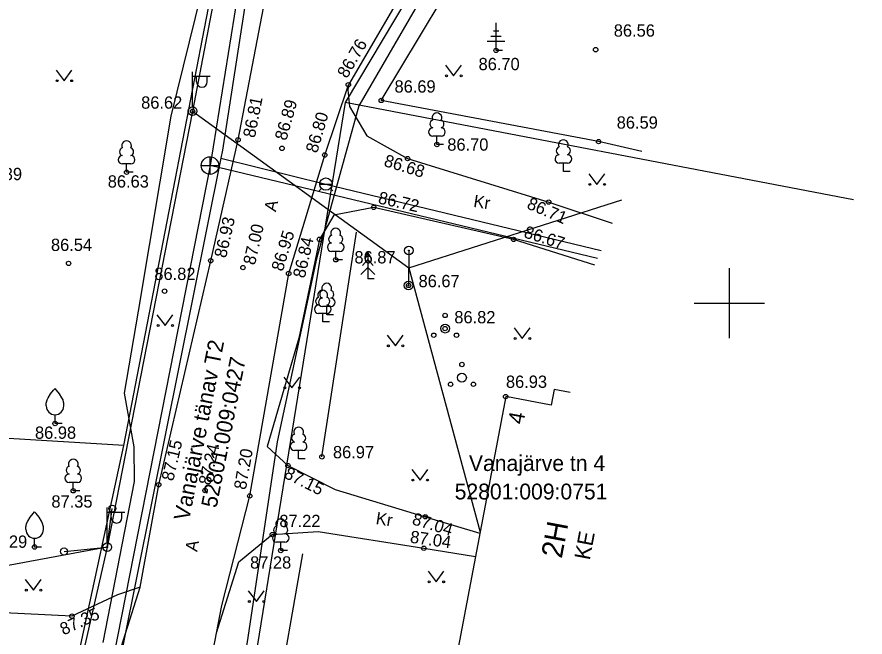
# Model space of a CAD drawing. Extents: x 648748 to 649126, y 6457789 to 6458252.
# Drawn here: x 648959.42 to 649007.73, y 6458080.98 to 6458116.31 of the extents above; entities that cross this region are included whole.
import ezdxf

# ---------------------------------------------------------------- set-up
doc = ezdxf.new("R2010")
doc.units = 0
for name, color, linetype in [('HALJASTUS', 7, 'Continuous'), ('HOONE', 7, 'Continuous'), ('KKAEV', 7, 'Continuous'), ('KORGUS-EH2000', 7, 'Continuous'), ('KTRASS', 7, 'Continuous'), ('MPOHULIIN', 7, 'Continuous'), ('PIIR', 7, 'Continuous'), ('POST', 7, 'Continuous'), ('PUU', 7, 'Continuous'), ('SITRASS', 7, 'Continuous'), ('TEE', 7, 'Continuous'), ('VKAEV', 7, 'Continuous'), ('VORK', 7, 'Continuous'), ('VTRASS', 7, 'Continuous')]:
    doc.layers.add(name, color=color, linetype=linetype)

msp = doc.modelspace()

# ---------------------------------------------------------------- linework, layer by layer
at = {"layer": 'HALJASTUS'}
for p, q in [((648961.649, 6458113.286), (648962.112, 6458112.679)), ((648962.112, 6458112.679), (648962.558, 6458113.286)), ((648983.834, 6458113.566), (648984.298, 6458112.96)), ((648984.298, 6458112.96), (648984.743, 6458113.566)), ((648992.001, 6458107.379), (648992.465, 6458106.772)), ((648992.465, 6458106.772), (648992.91, 6458107.379)), ((648976.796, 6458091.246), (648978.769, 6458104.056)), ((648967.4, 6458099.328), (648967.864, 6458098.722)), ((648967.864, 6458098.722), (648968.309, 6458099.328)), ((648987.742, 6458098.595), (648988.205, 6458097.988)), ((648988.205, 6458097.988), (648988.651, 6458098.595)), ((648980.518, 6458098.174), (648980.981, 6458097.568)), ((648980.981, 6458097.568), (648981.427, 6458098.174)), ((648974.626, 6458095.789), (648975.089, 6458095.183)), ((648975.089, 6458095.183), (648975.535, 6458095.789)), ((648981.92, 6458090.529), (648982.384, 6458089.923)), ((648982.384, 6458089.923), (648982.829, 6458090.529)), ((648982.84, 6458084.728), (648983.303, 6458084.121)), ((648983.303, 6458084.121), (648983.749, 6458084.728)), ((648959.895, 6458084.248), (648960.359, 6458083.642)), ((648960.359, 6458083.642), (648960.804, 6458084.248)), ((648972.6, 6458083.606), (648973.063, 6458082.999)), ((648973.063, 6458082.999), (648973.509, 6458083.606))]:
    msp.add_line(p, q, dxfattribs=at)
for points in [[(648995.014, 6458108.651), (648992.555, 6458109.206), (648980.179, 6458111.553), (648985.889, 6458121.059), (648992.136, 6458131.694), (648995.514, 6458136.968)], [(648972.606, 6458069.282), (648974.136, 6458076.713), (648975.715, 6458085.722)]]:
    msp.add_lwpolyline(points, dxfattribs=at)
for centre in [(648961.711, 6458112.679), (648962.54, 6458112.679), (648983.897, 6458112.96), (648984.726, 6458112.96), (648992.064, 6458106.772), (648992.893, 6458106.772), (648967.463, 6458098.722), (648968.292, 6458098.722), (648987.804, 6458097.988), (648988.633, 6458097.988), (648980.58, 6458097.568), (648981.409, 6458097.568), (648974.688, 6458095.183), (648975.517, 6458095.183), (648981.983, 6458089.923), (648982.812, 6458089.923), (648982.902, 6458084.121), (648983.731, 6458084.121), (648959.958, 6458083.642), (648960.787, 6458083.642), (648972.662, 6458082.999), (648973.491, 6458082.999)]:
    msp.add_circle(centre, 0.055, dxfattribs=at)
at = {"layer": 'HOONE'}
msp.add_lwpolyline([(648990.937, 6458094.909), (648990.022, 6458095.086), (648989.853, 6458094.19), (648987.264, 6458094.679), (648984.216, 6458078.561), (648986.916, 6458078.05), (648986.751, 6458077.176), (648988.913, 6458076.768)], dxfattribs=at)
at = {"layer": 'KKAEV'}
for p, q in [((648970.422, 6458107.342), (648970.422, 6458108.342)), ((648969.922, 6458107.842), (648970.922, 6458107.842))]:
    msp.add_line(p, q, dxfattribs=at)
msp.add_circle((648970.422, 6458107.842), 0.5, dxfattribs=at)
at = {"layer": 'KORGUS-EH2000'}
for centre in [(648986.716, 6458114.406), (648992.39, 6458114.447), (648978.301, 6458112.451), (648980.179, 6458111.553), (648969.428, 6458110.939), (648972.022, 6458109.308), (648992.555, 6458109.206), (648974.522, 6458108.824), (648983.347, 6458109.043), (648976.958, 6458108.444), (648981.678, 6458108.238), (648965.668, 6458107.461), (648979.746, 6458105.46), (648989.713, 6458105.763), (648976.658, 6458103.639), (648987.716, 6458103.635), (648977.582, 6458102.473), (648962.363, 6458102.27), (648970.461, 6458102.422), (648972.295, 6458102.031), (648974.902, 6458101.691), (648981.734, 6458101.01), (648967.833, 6458100.686), (648983.814, 6458098.551), (648987.264, 6458094.679), (648961.593, 6458093.144), (648976.796, 6458091.246), (648974.858, 6458090.743), (648967.5, 6458089.655), (648962.634, 6458089.31), (648970.142, 6458089.327), (648972.682, 6458089.018), (648982.682, 6458087.834), (648973.97, 6458086.815), (648960.43, 6458086.106), (648982.601, 6458086.036), (648974.448, 6458085.905), (648962.555, 6458082.165)]:
    msp.add_circle(centre, 0.125, dxfattribs=at)
at = {"layer": 'KTRASS'}
for p, q in [((648975.244, 6458137.772), (648970.422, 6458107.842)), ((648970.422, 6458107.842), (648961.748, 6458063.747)), ((648992.504, 6458102.546), (648970.422, 6458107.842))]:
    msp.add_line(p, q, dxfattribs=at)
at = {"layer": 'MPOHULIIN'}
msp.add_line((648964.567, 6458086.1), (648917.398, 6458077.299), dxfattribs=at)
for points in [[(648980.689, 6458168.372), (648973.79, 6458133.816), (648969.428, 6458110.939), (648964.567, 6458086.1), (648960.388, 6458067.751), (648949.192, 6458062.065)], [(648969.428, 6458110.939), (648981.739, 6458102.008), (648985.804, 6458086.956)], [(648981.739, 6458102.008), (648993.878, 6458105.888)]]:
    msp.add_lwpolyline(points, dxfattribs=at)
at = {"layer": 'PIIR'}
for p, q in [((649001.06, 6458149.93), (648978.12, 6458111.43)), ((648965.52, 6458091.89), (648973.5, 6458133.18)), ((648978.12, 6458111.43), (648971.21, 6458068.79)), ((649007.07, 6458105.881), (648978.12, 6458111.43)), ((648965.52, 6458091.89), (648918.81, 6458094.69)), ((648955.2, 6458044.42), (648965.52, 6458091.89))]:
    msp.add_line(p, q, dxfattribs=at)
at = {"layer": 'POST'}
for p, q in [((648969.428, 6458111.189), (648969.428, 6458113.189)), ((648969.428, 6458112.939), (648970.428, 6458112.939)), ((648969.655, 6458112.618), (648969.655, 6458112.939)), ((648970.268, 6458112.618), (648970.268, 6458112.939)), ((648981.744, 6458103.006), (648981.734, 6458101.01)), ((648964.567, 6458086.35), (648964.567, 6458088.35)), ((648964.567, 6458088.1), (648965.567, 6458088.1)), ((648964.793, 6458087.779), (648964.793, 6458088.1)), ((648965.406, 6458087.779), (648965.406, 6458088.1))]:
    msp.add_line(p, q, dxfattribs=at)
msp.add_lwpolyline([(648962.105, 6458085.851), (648964.567, 6458086.1), (648964.852, 6458088.295)], dxfattribs=at)
for centre, radius in [((648969.428, 6458110.939), 0.25), ((648969.428, 6458110.939), 0.0234), ((648981.744, 6458103.006), 0.25), ((648981.744, 6458103.006), 0.0234), ((648981.734, 6458101.01), 0.25), ((648981.734, 6458101.01), 0.0234), ((648964.852, 6458088.295), 0.2), ((648964.567, 6458086.1), 0.25), ((648962.105, 6458085.851), 0.2), ((648964.567, 6458086.1), 0.0234)]:
    msp.add_circle(centre, radius, dxfattribs=at)
for centre in [(648969.961, 6458112.618), (648965.1, 6458087.779)]:
    msp.add_arc(centre, 0.306, 180, 0, dxfattribs=at)
at = {"layer": 'PUU'}
for p, q in [((648986.716, 6458114.406), (648986.716, 6458115.981)), ((648987.016, 6458115.206), (648986.416, 6458115.206)), ((648986.866, 6458115.506), (648986.566, 6458115.506)), ((648987.216, 6458114.906), (648986.216, 6458114.906)), ((648987.076, 6458114.406), (648986.716, 6458114.406)), ((648983.587, 6458109.518), (648983.107, 6458109.518)), ((648983.347, 6458109.043), (648983.347, 6458109.518)), ((648983.727, 6458109.043), (648983.347, 6458109.043)), ((648965.908, 6458107.936), (648965.428, 6458107.936)), ((648965.668, 6458107.461), (648965.668, 6458107.936)), ((648990.789, 6458107.985), (648990.309, 6458107.985)), ((648990.549, 6458107.51), (648990.549, 6458107.985)), ((648966.048, 6458107.461), (648965.668, 6458107.461)), ((648990.929, 6458107.51), (648990.549, 6458107.51)), ((648977.822, 6458102.948), (648977.342, 6458102.948)), ((648977.582, 6458102.473), (648977.582, 6458102.948)), ((648979.416, 6458102.89), (648979.266, 6458102.64)), ((648979.566, 6458102.64), (648979.416, 6458102.89)), ((648979.416, 6458102.89), (648979.416, 6458101.39)), ((648977.962, 6458102.473), (648977.582, 6458102.473)), ((648979.416, 6458102.49), (648979.116, 6458102.14)), ((648979.716, 6458102.14), (648979.416, 6458102.49)), ((648979.416, 6458102.04), (648979.016, 6458101.64)), ((648979.816, 6458101.64), (648979.416, 6458102.04)), ((648979.776, 6458101.39), (648979.416, 6458101.39)), ((648977.312, 6458099.811), (648976.832, 6458099.811)), ((648977.072, 6458099.336), (648977.072, 6458099.811)), ((648977.08, 6458099.414), (648976.6, 6458099.414)), ((648976.84, 6458098.939), (648976.84, 6458099.414)), ((648977.452, 6458099.336), (648977.072, 6458099.336)), ((648977.22, 6458098.939), (648976.84, 6458098.939)), ((648961.593, 6458093.144), (648961.593, 6458093.644)), ((648961.993, 6458093.144), (648961.593, 6458093.144)), ((648975.711, 6458091.613), (648975.231, 6458091.613)), ((648975.471, 6458091.138), (648975.471, 6458091.613)), ((648975.851, 6458091.138), (648975.471, 6458091.138)), ((648962.874, 6458089.785), (648962.394, 6458089.785)), ((648962.634, 6458089.31), (648962.634, 6458089.785)), ((648963.014, 6458089.31), (648962.634, 6458089.31)), ((648960.43, 6458086.106), (648960.43, 6458086.606)), ((648974.688, 6458086.38), (648974.208, 6458086.38)), ((648974.448, 6458085.905), (648974.448, 6458086.38)), ((648960.83, 6458086.106), (648960.43, 6458086.106)), ((648974.828, 6458085.905), (648974.448, 6458085.905))]:
    msp.add_line(p, q, dxfattribs=at)
for points in [[(648961.093, 6458094.144), (648961.093, 6458094.294), (648961.103, 6458094.359), (648961.138, 6458094.489), (648961.198, 6458094.609), (648961.343, 6458094.844), (648961.503, 6458095.049), (648961.593, 6458095.144)], [(648962.093, 6458094.144), (648962.093, 6458094.294), (648962.083, 6458094.359), (648962.048, 6458094.489), (648961.988, 6458094.609), (648961.843, 6458094.844), (648961.683, 6458095.049), (648961.593, 6458095.144)], [(648959.93, 6458087.106), (648959.93, 6458087.256), (648959.94, 6458087.321), (648959.975, 6458087.451), (648960.035, 6458087.571), (648960.18, 6458087.806), (648960.34, 6458088.011), (648960.43, 6458088.106)], [(648960.93, 6458087.106), (648960.93, 6458087.256), (648960.92, 6458087.321), (648960.885, 6458087.451), (648960.825, 6458087.571), (648960.68, 6458087.806), (648960.52, 6458088.011), (648960.43, 6458088.106)]]:
    msp.add_lwpolyline(points, dxfattribs=at)
for centre, radius in [((648983.814, 6458099.301), 0.125), ((648983.814, 6458098.551), 0.25), ((648983.164, 6458098.176), 0.125), ((648984.464, 6458098.176), 0.125), ((648984.773, 6458096.508), 0.125), ((648984.773, 6458095.758), 0.25), ((648984.123, 6458095.383), 0.125), ((648985.423, 6458095.383), 0.125)]:
    msp.add_circle(centre, radius, dxfattribs=at)
for centre, radius, start, end in [((648983.347, 6458110.563), 0.277, 332.58, 207.42), ((648983.177, 6458110.215), 0.233, 109.022, 253.142), ((648983.517, 6458110.215), 0.233, 286.851, 70.986), ((648983.109, 6458109.755), 0.238, 90.002, 269.395), ((648983.584, 6458109.755), 0.238, 270.605, 89.998), ((648965.498, 6458108.633), 0.233, 109.022, 253.142), ((648965.668, 6458108.981), 0.277, 332.58, 207.42), ((648965.838, 6458108.633), 0.233, 286.851, 70.986), ((648990.379, 6458108.682), 0.233, 109.022, 253.142), ((648990.549, 6458109.03), 0.277, 332.58, 207.42), ((648990.719, 6458108.682), 0.233, 286.851, 70.986), ((648965.431, 6458108.173), 0.238, 90.002, 269.395), ((648965.906, 6458108.173), 0.238, 270.605, 89.998), ((648990.312, 6458108.222), 0.238, 90.002, 269.395), ((648990.787, 6458108.222), 0.238, 270.605, 89.998), ((648977.582, 6458103.993), 0.277, 332.58, 207.42), ((648977.412, 6458103.646), 0.233, 109.022, 253.142), ((648977.752, 6458103.646), 0.233, 286.851, 70.986), ((648977.344, 6458103.186), 0.238, 90.002, 269.395), ((648977.819, 6458103.186), 0.238, 270.605, 89.998), ((648977.072, 6458100.856), 0.277, 332.58, 207.42), ((648976.84, 6458100.459), 0.277, 332.58, 207.42), ((648976.902, 6458100.509), 0.233, 109.022, 253.142), ((648977.242, 6458100.509), 0.233, 286.851, 70.986), ((648976.67, 6458100.112), 0.233, 109.022, 253.142), ((648976.835, 6458100.049), 0.238, 90.002, 269.395), ((648977.01, 6458100.112), 0.233, 286.851, 70.986), ((648977.31, 6458100.049), 0.238, 270.605, 89.998), ((648976.603, 6458099.652), 0.238, 90.002, 269.395), ((648977.078, 6458099.652), 0.238, 270.605, 89.998), ((648961.593, 6458094.144), 0.5, 180, 0), ((648975.471, 6458092.658), 0.277, 332.58, 207.42), ((648975.301, 6458092.311), 0.233, 109.022, 253.142), ((648975.641, 6458092.311), 0.233, 286.851, 70.986), ((648975.233, 6458091.851), 0.238, 90.002, 269.395), ((648975.708, 6458091.851), 0.238, 270.605, 89.998), ((648962.634, 6458090.83), 0.277, 332.58, 207.42), ((648962.464, 6458090.483), 0.233, 109.022, 253.142), ((648962.804, 6458090.483), 0.233, 286.851, 70.986), ((648962.396, 6458090.023), 0.238, 90.002, 269.395), ((648962.871, 6458090.023), 0.238, 270.605, 89.998), ((648974.448, 6458087.425), 0.277, 332.58, 207.42), ((648960.43, 6458087.106), 0.5, 180, 0), ((648974.278, 6458087.077), 0.233, 109.022, 253.142), ((648974.618, 6458087.077), 0.233, 286.851, 70.986), ((648974.211, 6458086.617), 0.238, 90.002, 269.395), ((648974.686, 6458086.617), 0.238, 270.605, 89.998)]:
    msp.add_arc(centre, radius, start, end, dxfattribs=at)
at = {"layer": 'SITRASS'}
for points in [[(648967.592, 6458140.769), (648970.954, 6458139.072), (648971.562, 6458136.232), (648972.057, 6458127.987), (648971.319, 6458123.389), (648968.181, 6458110.649), (648966.331, 6458099.547), (648965.537, 6458094.866), (648966.077, 6458091.823), (648966.11, 6458089.841), (648964.318, 6458080.667)], [(648995.643, 6458121.195), (648984.834, 6458121.422), (648983.821, 6458119.744), (648978.901, 6458111.244), (648976.485, 6458102.526), (648974.256, 6458092.094), (648972.583, 6458080.942), (648971.63, 6458075.06), (648971.122, 6458066.021), (648973.701, 6458061.391), (648978.778, 6458055.16), (648981.628, 6458053.906), (648983.341, 6458058.682), (648986.212, 6458060.495)]]:
    msp.add_lwpolyline(points, dxfattribs=at)
at = {"layer": 'TEE'}
for points in [[(648964.651, 6458078.174), (648966.451, 6458083.821), (648967.5, 6458089.655), (648970.461, 6458102.422), (648972.022, 6458109.308), (648974.38, 6458121.59), (648976.218, 6458132.059), (648976.233, 6458135.434), (648975.702, 6458138.304), (648974.226, 6458140.713), (648971.86, 6458143.333), (648969.445, 6458145.153), (648966.422, 6458144.919), (648958.871, 6458143.041), (648949.896, 6458140.146), (648946.296, 6458138.815), (648935.488, 6458134.684), (648924.063, 6458130.013), (648903.056, 6458121.74), (648892.363, 6458117.796), (648888.636, 6458116.575), (648879.911, 6458112.582)], [(648995.602, 6458137.331), (648993.894, 6458138.414), (648989.291, 6458130.767), (648983.389, 6458121.145), (648978.301, 6458112.451)], [(649004.65, 6458042.504), (649002.764, 6458040.8), (649000.886, 6458039.29), (648996.637, 6458043.334), (648995.949, 6458042.696), (649001.007, 6458037.421), (649007.735, 6458029.828), (649001.193, 6458023.903), (648995.967, 6458030.098), (648989.468, 6458038.405), (648983.655, 6458045.376), (648980.163, 6458049.435), (648973.986, 6458057.003), (648970.576, 6458062.405), (648968.747, 6458067.645), (648969.273, 6458073.286), (648971.089, 6458082.764), (648972.682, 6458089.018), (648974.902, 6458101.691), (648976.958, 6458108.444), (648978.301, 6458112.451)], [(648978.301, 6458112.451), (648978.264, 6458112.152), (648978.375, 6458111.204), (648979.351, 6458109.545), (648981.678, 6458108.238), (648989.713, 6458105.763), (648993.331, 6458104.557)], [(648992.347, 6458102.164), (648987.716, 6458103.635), (648979.746, 6458105.46), (648977.48, 6458105.016), (648976.658, 6458103.639), (648975.473, 6458098.009), (648973.678, 6458091.83), (648974.858, 6458090.743), (648977.557, 6458089.386), (648982.682, 6458087.834), (648985.792, 6458086.892)], [(648970.791, 6458081.208), (648972.072, 6458085.268), (648973.97, 6458086.815), (648976.579, 6458086.983), (648982.601, 6458086.036), (648985.542, 6458085.574)], [(648966.451, 6458083.821), (648965.158, 6458083.372), (648962.555, 6458082.165)], [(648962.555, 6458082.165), (648950.584, 6458082.755), (648950.441, 6458079.851), (648956.296, 6458079.563)]]:
    msp.add_lwpolyline(points, dxfattribs=at)
at = {"layer": 'VKAEV'}
for p, q in [((648976.781, 6458106.543), (648976.641, 6458106.403)), ((648976.678, 6458106.79), (648977.378, 6458106.79)), ((648977.276, 6458106.543), (648977.415, 6458106.403))]:
    msp.add_line(p, q, dxfattribs=at)
msp.add_circle((648977.028, 6458106.79), 0.35, dxfattribs=at)
at = {"layer": 'VORK'}
for p, q in [((649000, 6458102), (649000, 6458098)), ((648998, 6458100), (649002, 6458100))]:
    msp.add_line(p, q, dxfattribs=at)
at = {"layer": 'VTRASS'}
for points in [[(648975.797, 6458138.798), (648975.753, 6458138.516), (648971.13, 6458108.715), (648971.04, 6458108.27), (648962.304, 6458064.78), (648962.245, 6458064.485), (648962.127, 6458064.182)], [(648971.04, 6458108.27), (648977.028, 6458106.79), (648992.696, 6458103.011)]]:
    msp.add_lwpolyline(points, dxfattribs=at)

# ---------------------------------------------------------------- texts
at = {"layer": 'HOONE'}
for s, height, p in [('4', 0.9, (648988.266, 6458093.058)), ('2H', 1.2, (648990.457, 6458085.419)), ('KE', 0.9, (648992.05, 6458085.325))]:
    msp.add_text(s, height=height, rotation=79.2926, dxfattribs=at).set_placement(p)
at = {"layer": 'KORGUS-EH2000'}
for s, p in [('86.56', (648993.422, 6458115.189)), ('86.70', (648985.719, 6458113.279)), ('86.69', (648980.931, 6458112.001)), ('86.62', (648966.498, 6458111.084)), ('86.59', (648993.588, 6458109.947)), ('86.70', (648983.938, 6458108.69)), ('86.39', (648957.372, 6458107.012)), ('86.63', (648964.596, 6458106.589)), ('86.54', (648961.361, 6458102.976)), ('86.87', (648978.649, 6458102.268)), ('86.82', (648967.252, 6458101.322)), ('86.67', (648982.3, 6458100.911)), ('86.82', (648984.338, 6458098.854)), ('86.93', (648987.279, 6458095.175)), ('86.98', (648960.451, 6458092.273)), ('86.97', (648977.425, 6458091.163)), ('87.35', (648961.386, 6458088.351)), ('87.22', (648974.371, 6458087.241)), ('87.29', (648957.665, 6458086.063)), ('87.28', (648972.705, 6458084.875))]:
    msp.add_text(s, height=0.7, dxfattribs=at).set_placement(p)
for s, rotation, p in [('86.76', 59.6596, (648978.222, 6458112.769)), ('86.81', 79.1317, (648972.979, 6458109.392)), ('86.89', 74.1676, (648974.765, 6458109.227)), ('86.80', 73.7798, (648976.526, 6458108.517)), ('86.68', 342.8806, (648980.28, 6458107.829)), ('86.72', 347.1036, (648979.957, 6458105.699)), ('86.71', 336.6511, (648988.419, 6458105.421)), ('86.93', 77.23, (648971.334, 6458102.54)), ('87.00', 77.23, (648972.98, 6458102.138)), ('86.95', 73.0699, (648974.564, 6458101.773)), ('86.67', 342.3808, (648988.257, 6458103.762)), ('86.84', 77.3742, (648975.818, 6458101.391)), ('87.15', 76.9431, (648968.326, 6458089.829)), ('87.24', 76.9431, (648970.435, 6458089.593)), ('87.20', 80.0655, (648972.463, 6458089.338)), ('87.15', 333.2976, (648974.583, 6458090.08)), ('87.04', 343.1526, (648981.886, 6458087.411)), ('87.04', 351.8361, (648981.786, 6458086.361)), ('87.35', 24.8732, (648962.075, 6458081.063))]:
    msp.add_text(s, height=0.7, rotation=rotation, dxfattribs=at).set_placement(p)
at = {"layer": 'PIIR'}
for s, rotation, p in [('Vanajärve tänav T2', 78.9136, (648969.227, 6458087.563)), ('52801:009:0427', 78.9136, (648970.792, 6458088.293)), ('Vanajärve tn 4', 360, (648985.171, 6458090.437)), ('52801:009:0751', 360, (648984.359, 6458088.818))]:
    msp.add_text(s, height=0.9, rotation=rotation, dxfattribs=at).set_placement(p)
at = {"layer": 'TEE'}
for s, rotation, p in [('Kr', 351.0641, (648985.396, 6458105.49)), ('A', 77.23, (648974.172, 6458105.178)), ('Kr', 351.0641, (648979.833, 6458087.417)), ('A', 79.8077, (648969.686, 6458085.811))]:
    msp.add_text(s, height=0.7, rotation=rotation, dxfattribs=at).set_placement(p)

doc.saveas('drawing.dxf')
